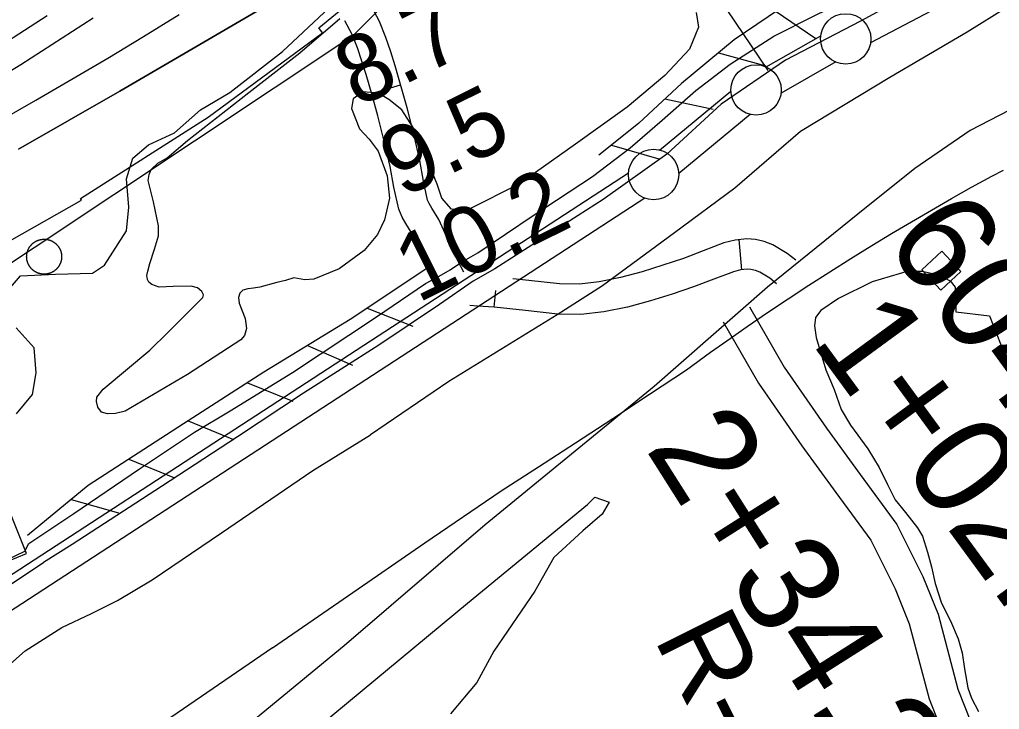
# Model space of a CAD drawing. Extents: x 3715084 to 3753216, y 488173 to 513963.
# Drawn here: x 3731429 to 3732401, y 498105 to 498790 of the extents above; entities that cross this region are included whole.
import ezdxf

# ---------------------------------------------------------------- set-up
doc = ezdxf.new("R2010")
doc.units = 0
for name, color, linetype in [('V-BLDG-OTLN', 7, 'Continuous'), ('V-CHAN-DOCK', 7, 'Continuous'), ('V-FLOD-BASE', 7, 'Continuous'), ('V-LEVE-TOET', 7, 'Continuous'), ('V-RAIL-TRAK', 7, 'Continuous'), ('V-RIVR-EDGE', 7, 'Continuous'), ('V-RIVR-RANG', 7, 'Continuous'), ('V-RIVR-RANG-IDEN', 7, 'Continuous'), ('V-ROAD-CNTR', 7, 'Continuous'), ('V-RRAP-FSHR', 7, 'Continuous'), ('V-RRAP-RVMT', 7, 'Continuous'), ('V-SITE-VEGE', 7, 'Continuous'), ('V-SURV-IDEN', 7, 'Continuous'), ('V-SURV-LINE', 7, 'Continuous'), ('V-TOPO-DPTH', 7, 'Continuous'), ('V-TOPO-MINR', 7, 'Continuous'), ('V-TOPO-SHOR', 7, 'Continuous'), ('V-TOPO-WATR', 7, 'Continuous')]:
    doc.layers.add(name, color=color, linetype=linetype)

msp = doc.modelspace()

# ---------------------------------------------------------------- linework, layer by layer
at = {"layer": 'V-BLDG-OTLN'}
msp.add_lwpolyline([(3732324.12, 498541.61), (3732343.99, 498560.18), (3732362.92, 498539.94), (3732343.04, 498521.36)], close=True, dxfattribs=at)
at = {"layer": 'V-CHAN-DOCK'}
for points in [[(3731436.97, 498560.3), (3731437.07, 498560.59), (3731437.17, 498560.87), (3731437.29, 498561.15), (3731437.4, 498561.43), (3731437.52, 498561.71), (3731437.65, 498561.98), (3731437.78, 498562.26), (3731437.91, 498562.53), (3731438.05, 498562.8), (3731438.2, 498563.07), (3731438.34, 498563.33), (3731438.5, 498563.59), (3731438.66, 498563.85), (3731438.82, 498564.1), (3731438.98, 498564.35), (3731439.16, 498564.6), (3731439.33, 498564.85), (3731439.51, 498565.09), (3731439.7, 498565.33), (3731439.89, 498565.57), (3731440.08, 498565.8), (3731440.27, 498566.04), (3731440.47, 498566.26), (3731440.68, 498566.48), (3731440.89, 498566.71), (3731441.1, 498566.92), (3731441.31, 498567.13), (3731441.53, 498567.34), (3731441.76, 498567.55), (3731441.98, 498567.75), (3731442.21, 498567.94), (3731442.45, 498568.14), (3731442.69, 498568.33), (3731442.93, 498568.51), (3731443.17, 498568.69), (3731443.41, 498568.86), (3731443.66, 498569.04), (3731443.92, 498569.21), (3731444.17, 498569.37), (3731444.43, 498569.53), (3731444.69, 498569.68), (3731444.96, 498569.83), (3731445.22, 498569.97), (3731445.49, 498570.11), (3731445.76, 498570.25), (3731446.03, 498570.38), (3731446.31, 498570.51), (3731446.58, 498570.63), (3731446.87, 498570.74), (3731447.15, 498570.85), (3731447.43, 498570.96), (3731447.71, 498571.06), (3731448, 498571.16), (3731448.29, 498571.25), (3731448.58, 498571.33), (3731448.87, 498571.41), (3731449.17, 498571.49), (3731449.46, 498571.56), (3731449.75, 498571.62), (3731450.05, 498571.69), (3731450.35, 498571.74), (3731450.65, 498571.79), (3731450.95, 498571.84), (3731451.25, 498571.88), (3731451.55, 498571.91), (3731451.85, 498571.94), (3731452.15, 498571.96), (3731452.45, 498571.98), (3731452.76, 498572), (3731453.06, 498572), (3731453.36, 498572.01), (3731453.67, 498572), (3731453.97, 498572), (3731454.27, 498571.98), (3731454.57, 498571.97), (3731454.87, 498571.94), (3731455.18, 498571.91), (3731455.48, 498571.88), (3731455.78, 498571.84), (3731456.08, 498571.79), (3731456.37, 498571.74), (3731456.67, 498571.69), (3731456.97, 498571.63), (3731457.26, 498571.56), (3731457.56, 498571.49), (3731457.85, 498571.42), (3731458.14, 498571.34), (3731458.44, 498571.25), (3731458.72, 498571.16), (3731459.01, 498571.06), (3731459.29, 498570.96), (3731459.58, 498570.86), (3731459.86, 498570.75), (3731460.14, 498570.63), (3731460.42, 498570.51), (3731460.69, 498570.38), (3731460.97, 498570.26), (3731461.24, 498570.12), (3731461.51, 498569.98), (3731461.77, 498569.84)], [(3731461.77, 498569.84), (3731462.04, 498569.69), (3731462.3, 498569.53), (3731462.56, 498569.38), (3731462.81, 498569.21), (3731463.06, 498569.04), (3731463.31, 498568.88), (3731463.56, 498568.7), (3731463.8, 498568.52), (3731464.04, 498568.33), (3731464.28, 498568.15), (3731464.51, 498567.95), (3731464.74, 498567.76), (3731464.97, 498567.56), (3731465.19, 498567.35), (3731465.41, 498567.14), (3731465.63, 498566.93), (3731465.84, 498566.72), (3731466.05, 498566.5), (3731466.25, 498566.27), (3731466.45, 498566.05), (3731466.65, 498565.82), (3731466.85, 498565.58), (3731467.03, 498565.35), (3731467.22, 498565.11), (3731467.4, 498564.86), (3731467.57, 498564.62), (3731467.75, 498564.37), (3731467.91, 498564.11), (3731468.07, 498563.86), (3731468.23, 498563.6), (3731468.39, 498563.34), (3731468.54, 498563.08), (3731468.68, 498562.81), (3731468.82, 498562.54), (3731468.96, 498562.27), (3731469.09, 498562), (3731469.21, 498561.72), (3731469.33, 498561.45), (3731469.45, 498561.17), (3731469.56, 498560.89), (3731469.67, 498560.6), (3731469.77, 498560.32), (3731469.86, 498560.03), (3731469.96, 498559.74), (3731470.04, 498559.45), (3731470.12, 498559.16), (3731470.2, 498558.86), (3731470.27, 498558.57), (3731470.33, 498558.28), (3731470.4, 498557.98), (3731470.45, 498557.68), (3731470.5, 498557.38), (3731470.54, 498557.08), (3731470.58, 498556.78), (3731470.62, 498556.48), (3731470.65, 498556.18), (3731470.67, 498555.88), (3731470.69, 498555.58), (3731470.7, 498555.27), (3731470.71, 498554.97)], [(3731450.66, 498537.53), (3731450.37, 498537.58), (3731450.07, 498537.63), (3731449.77, 498537.69), (3731449.48, 498537.76), (3731449.18, 498537.83), (3731448.89, 498537.91), (3731448.6, 498537.99), (3731448.31, 498538.07), (3731448.02, 498538.16), (3731447.73, 498538.26), (3731447.45, 498538.36), (3731447.16, 498538.47), (3731446.88, 498538.58), (3731446.6, 498538.69), (3731446.32, 498538.81), (3731446.05, 498538.94), (3731445.77, 498539.07), (3731445.5, 498539.2), (3731445.23, 498539.34), (3731444.97, 498539.49), (3731444.7, 498539.64), (3731444.44, 498539.79), (3731444.19, 498539.95), (3731443.93, 498540.11), (3731443.68, 498540.28), (3731443.43, 498540.45), (3731443.18, 498540.62), (3731442.94, 498540.8), (3731442.7, 498540.99), (3731442.46, 498541.18), (3731442.23, 498541.37), (3731442, 498541.57), (3731441.77, 498541.77), (3731441.55, 498541.97), (3731441.33, 498542.18), (3731441.11, 498542.39), (3731440.9, 498542.61), (3731440.69, 498542.83), (3731440.48, 498543.05), (3731440.28, 498543.28), (3731440.09, 498543.51), (3731439.89, 498543.74), (3731439.71, 498543.98), (3731439.52, 498544.22), (3731439.34, 498544.46), (3731439.17, 498544.71), (3731439, 498544.96), (3731438.83, 498545.21), (3731438.66, 498545.46), (3731438.5, 498545.72), (3731438.35, 498545.98), (3731438.2, 498546.25), (3731438.06, 498546.51), (3731437.92, 498546.78), (3731437.78, 498547.05), (3731437.65, 498547.32), (3731437.53, 498547.6), (3731437.41, 498547.88), (3731437.29, 498548.16), (3731437.18, 498548.44), (3731437.07, 498548.72), (3731436.97, 498549.01), (3731436.88, 498549.29), (3731436.79, 498549.58), (3731436.7, 498549.87), (3731436.62, 498550.16), (3731436.54, 498550.46), (3731436.47, 498550.75), (3731436.4, 498551.05), (3731436.35, 498551.34), (3731436.29, 498551.64), (3731436.24, 498551.94), (3731436.2, 498552.24), (3731436.15, 498552.54), (3731436.12, 498552.84), (3731436.09, 498553.14), (3731436.07, 498553.44), (3731436.05, 498553.75), (3731436.04, 498554.05), (3731436.03, 498554.35), (3731436.02, 498554.65), (3731436.03, 498554.96), (3731436.04, 498555.26), (3731436.05, 498555.56), (3731436.07, 498555.86), (3731436.09, 498556.17), (3731436.12, 498556.47), (3731436.15, 498556.77), (3731436.19, 498557.07), (3731436.24, 498557.37), (3731436.29, 498557.67), (3731436.34, 498557.96), (3731436.4, 498558.26), (3731436.47, 498558.55), (3731436.54, 498558.85), (3731436.61, 498559.14), (3731436.7, 498559.44), (3731436.78, 498559.73), (3731436.87, 498560.02), (3731436.97, 498560.3)], [(3731470.71, 498554.97), (3731470.71, 498554.67), (3731470.71, 498554.37), (3731470.7, 498554.06), (3731470.69, 498553.76), (3731470.67, 498553.46), (3731470.65, 498553.16), (3731470.62, 498552.85), (3731470.59, 498552.55), (3731470.55, 498552.26), (3731470.5, 498551.96), (3731470.45, 498551.66), (3731470.4, 498551.36), (3731470.34, 498551.06), (3731470.27, 498550.77), (3731470.2, 498550.47), (3731470.13, 498550.18), (3731470.04, 498549.89), (3731469.96, 498549.6), (3731469.87, 498549.31), (3731469.77, 498549.02), (3731469.67, 498548.74), (3731469.56, 498548.45), (3731469.46, 498548.17), (3731469.34, 498547.89), (3731469.22, 498547.61), (3731469.09, 498547.34), (3731468.96, 498547.07), (3731468.83, 498546.79), (3731468.69, 498546.53), (3731468.54, 498546.26), (3731468.39, 498545.99), (3731468.24, 498545.73), (3731468.08, 498545.48), (3731467.92, 498545.22), (3731467.75, 498544.97), (3731467.58, 498544.72), (3731467.41, 498544.47), (3731467.23, 498544.23), (3731467.04, 498543.99), (3731466.85, 498543.75), (3731466.66, 498543.52), (3731466.46, 498543.29), (3731466.26, 498543.06), (3731466.06, 498542.84), (3731465.85, 498542.62), (3731465.64, 498542.4), (3731465.42, 498542.19), (3731465.21, 498541.98), (3731464.98, 498541.78), (3731464.75, 498541.58), (3731464.52, 498541.38), (3731464.29, 498541.19), (3731464.05, 498541), (3731463.81, 498540.81), (3731463.57, 498540.63), (3731463.33, 498540.46), (3731463.08, 498540.29), (3731462.82, 498540.12), (3731462.57, 498539.96), (3731462.31, 498539.8), (3731462.05, 498539.64), (3731461.79, 498539.49), (3731461.52, 498539.35), (3731461.25, 498539.21), (3731460.98, 498539.08), (3731460.71, 498538.95), (3731460.43, 498538.82), (3731460.16, 498538.7), (3731459.87, 498538.58), (3731459.59, 498538.47), (3731459.31, 498538.37), (3731459.02, 498538.26), (3731458.74, 498538.17), (3731458.45, 498538.08), (3731458.16, 498537.99), (3731457.87, 498537.91), (3731457.57, 498537.83), (3731457.28, 498537.76), (3731456.98, 498537.7), (3731456.69, 498537.64), (3731456.39, 498537.58), (3731456.09, 498537.53), (3731455.79, 498537.49), (3731455.49, 498537.45), (3731455.19, 498537.41), (3731454.89, 498537.38), (3731454.59, 498537.36), (3731454.29, 498537.34), (3731453.98, 498537.33), (3731453.68, 498537.32), (3731453.38, 498537.32), (3731453.08, 498537.32), (3731452.77, 498537.33), (3731452.47, 498537.34), (3731452.17, 498537.36), (3731451.87, 498537.38), (3731451.56, 498537.41), (3731451.26, 498537.44), (3731450.96, 498537.48), (3731450.66, 498537.53)]]:
    msp.add_lwpolyline(points, dxfattribs=at)
at = {"layer": 'V-FLOD-BASE'}
for points in [[(3732385.46, 498860.31), (3732337.41, 498828.72), (3732263.44, 498788.3), (3732188.83, 498749.77), (3732124.98, 498706.17), (3732071.23, 498656.26), (3732008, 498611.4), (3731900.52, 498542.55), (3731879.03, 498530.54), (3731845.52, 498507.17)], [(3731845.52, 498507.17), (3731785.45, 498466.73), (3731710.85, 498419.36), (3731645.1, 498375.77), (3731569.86, 498326.49), (3731481.34, 498269), (3731452.89, 498251.31)], [(3731398.25, 498215.29), (3731452.89, 498251.31)]]:
    msp.add_lwpolyline(points, dxfattribs=at)
at = {"layer": 'V-LEVE-TOET'}
for points in [[(3731699.94, 498439.92), (3731783.04, 498494.86), (3731831.78, 498527.95), (3731843.03, 498534.19), (3731856.15, 498541.69), (3731867.4, 498549.18), (3731883.64, 498558.54), (3731938.63, 498595.38), (3731997.37, 498634.09), (3732034.86, 498662.81), (3732066.73, 498690.29), (3732099.85, 498719.64), (3732134.21, 498745.86), (3732177.33, 498773.33), (3732217.94, 498793.93), (3732277.92, 498823.27), (3732336.66, 498859.48), (3732367.27, 498876.96), (3732382.27, 498888.2), (3732392.9, 498894.45), (3732400.42, 498898.04)], [(3732408.66, 498801.82), (3732369.29, 498777.47), (3732292.44, 498732.52), (3732203.71, 498678.83), (3732138.72, 498622.63), (3732078.73, 498578.3), (3732007.5, 498525.85), (3731962.51, 498497.13), (3731855.04, 498430.95), (3731777.27, 498377.8)], [(3731438.34, 498269.98), (3731482.74, 498299.82), (3731547.84, 498344.3), (3731602.46, 498380.61), (3731638.1, 498401.88), (3731699.94, 498439.92)], [(3731500.42, 498200.57), (3731526.29, 498213.52), (3731560.43, 498234.21), (3731629.28, 498280.74), (3731720.04, 498342.39), (3731777.27, 498377.8)], [(3731358.16, 498221.77), (3731365, 498229.58), (3731434.35, 498262.4), (3731438.34, 498269.98)], [(3731222.63, 498010.08), (3731233.49, 498014.87), (3731298.21, 498058.22), (3731346.55, 498091.03), (3731358.59, 498097.4), (3731369.04, 498105.55), (3731387.57, 498122.23), (3731434.5, 498163.54), (3731470.8, 498186.62), (3731500.42, 498200.57)]]:
    msp.add_lwpolyline(points, dxfattribs=at)
at = {"layer": 'V-RAIL-TRAK'}
for points in [[(3732114.67, 498459.84), (3732130.7, 498471.26), (3732150.88, 498485.34), (3732171.2, 498499.22), (3732191.64, 498512.91), (3732212.22, 498526.41), (3732232.93, 498539.71), (3732253.76, 498552.8), (3732274.72, 498565.7), (3732294.27, 498577.62), (3732313.92, 498589.36), (3732333.68, 498600.93), (3732353.54, 498612.32), (3732373.5, 498623.52), (3732393.57, 498634.55), (3732405.39, 498640.37)], [(3731679.81, 498166.46), (3731755.37, 498218.61), (3731831.02, 498270.62), (3731906.77, 498322.49), (3731943.8, 498346.14), (3731980.71, 498369.97), (3732017.5, 498393.98), (3732054.18, 498418.16), (3732090.74, 498442.52), (3732114.67, 498459.84)], [(3731679.81, 498166.46), (3731555.77, 498081.73), (3731430.95, 497996.6), (3731300.41, 497909.09), (3731231.09, 497865.12)]]:
    msp.add_lwpolyline(points, dxfattribs=at)
at = {"layer": 'V-RIVR-EDGE'}
for points in [[(3731416.09, 498519.43), (3731429.94, 498535.6), (3731464.76, 498537.32), (3731501.39, 498538.43), (3731513.41, 498546.2), (3731535.11, 498580.37), (3731537.57, 498603.78), (3731535.24, 498632), (3731541.29, 498652.39), (3731556.93, 498665.56), (3731582.77, 498677.5), (3731608.64, 498700.25), (3731637.5, 498717.59), (3731689.83, 498758.28), (3731772.27, 498835.52)], [(3731426, 498398.74), (3731441.66, 498417.91), (3731445.31, 498439.51), (3731443.57, 498464.13), (3731425.61, 498483.99)], [(3731358.94, 498228.41), (3731435.86, 498260.04), (3731398.27, 498353.78)]]:
    msp.add_lwpolyline(points, dxfattribs=at)
at = {"layer": 'V-RIVR-RANG'}
msp.add_line((3732171.63, 498739.52), (3731602.8, 499586.19), dxfattribs=at)
at = {"layer": 'V-ROAD-CNTR'}
for p, q in [((3731778.31, 498716.69), (3731807.08, 498725.17)), ((3732145.77, 498541.7), (3732143.1, 498571.58)), ((3731899.77, 498504.61), (3731901.6, 498520.99))]:
    msp.add_line(p, q, dxfattribs=at)
for points in [[(3733715.57, 498954.14), (3733490.9, 498921.32), (3733259.48, 498888.54), (3733051.28, 498857.49), (3732876.96, 498828.74), (3732784.88, 498814.94), (3732717.77, 498804.69), (3732646.3, 498789.1), (3732562.5, 498763.31), (3732493.54, 498739.57), (3732430.27, 498709.84), (3732372.27, 498679.78), (3732317.45, 498642.1), (3732260.82, 498596.91), (3732170.98, 498524.46), (3732058.55, 498426.03), (3731890.92, 498288.7), (3731751.05, 498168.7), (3731580.79, 498028.32), (3731483.88, 497948.43), (3731408.15, 497888)], [(3731869.65, 498539.29), (3731864.16, 498549.95), (3731854.75, 498570.34), (3731844.9, 498591.65), (3731838.01, 498602.94), (3731835.39, 498607.38), (3731833.9, 498610.88), (3731829.84, 498629.54), (3731826.18, 498650.15), (3731820.07, 498676.32), (3731813.58, 498702.22), (3731807.67, 498723.18), (3731801.55, 498743.96), (3731797.23, 498757.92), (3731792.55, 498772.27), (3731786, 498788.11), (3731778.12, 498802.89)], [(3731844.51, 498522.6), (3731837.2, 498536.79), (3731827.52, 498557.76), (3731818.39, 498577.5), (3731812.29, 498587.5), (3731808.57, 498593.8), (3731805.19, 498601.72), (3731800.4, 498623.74), (3731796.79, 498644.11), (3731790.91, 498669.26), (3731784.58, 498694.5), (3731778.84, 498714.87), (3731772.82, 498735.29), (3731768.64, 498748.84), (3731764.38, 498761.87), (3731758.84, 498775.29), (3731751.65, 498788.76)], [(3732199.14, 498551.11), (3732190.73, 498558), (3732176.46, 498566.39), (3732167.87, 498569.63), (3732159.15, 498571.62), (3732150.73, 498572.26), (3732138.93, 498571.2), (3732127.93, 498568.26), (3732107.35, 498560.35), (3732087.73, 498552.99), (3732067.25, 498546.16), (3732046.67, 498539.64), (3732025.42, 498533.89), (3732004.12, 498529.61), (3731984.49, 498527.44), (3731964.85, 498527.77), (3731934.22, 498530.96), (3731918.49, 498532.71)], [(3732180.13, 498527.9), (3732173.51, 498533.32), (3732163.47, 498539.23), (3732159.21, 498540.83), (3732154.64, 498541.87), (3732150.93, 498542.16), (3732144.18, 498541.55), (3732137.22, 498539.69), (3732118, 498532.3), (3732097.75, 498524.71), (3732076.53, 498517.63), (3732055.12, 498510.85), (3732032.3, 498504.68), (3732008.73, 498499.94), (3731985.88, 498497.41), (3731963.04, 498497.8), (3731931.01, 498501.13), (3731900.02, 498504.58), (3731883.29, 498505.54), (3731875.91, 498506.32)], [(3732153.3, 498505.03), (3732187.59, 498445.12), (3732229.57, 498384.44), (3732263.14, 498338.54), (3732299.43, 498288.98), (3732325.18, 498237.51), (3732340.36, 498200.01), (3732360, 498125.44), (3732379.37, 498076.29)], [(3732127.26, 498490.13), (3732162.19, 498429.1), (3732205.12, 498367.05), (3732238.93, 498320.83), (3732273.73, 498273.3), (3732297.82, 498225.14), (3732311.84, 498190.52), (3732331.44, 498116.09), (3732351.46, 498065.29)]]:
    msp.add_lwpolyline(points, dxfattribs=at)
at = {"layer": 'V-RRAP-FSHR'}
for p, q in [((3732178.7, 498798.56), (3732219.18, 498771.25)), ((3732122.33, 498756.92), (3732169.47, 498744.17)), ((3732069.4, 498711.15), (3732117.15, 498700.95)), ((3732016.46, 498665.43), (3732063.31, 498651.69)), ((3731773.9, 498503.6), (3731819.35, 498485.73)), ((3731714.56, 498466.5), (3731759.3, 498446.94)), ((3731655.05, 498429.64), (3731700.25, 498411.16)), ((3731596.19, 498391.76), (3731641.38, 498373.28)), ((3731537.4, 498353.75), (3731582.65, 498335.38)), ((3731480.11, 498313.71), (3731527.16, 498300.63))]:
    msp.add_line(p, q, dxfattribs=at)
for points in [[(3728004.36, 498122.76), (3728249.57, 498078.76), (3728561.47, 498063.71), (3728941.93, 498053.37), (3729895.33, 498086.11), (3730231.16, 498125.42), (3730543.47, 498170.09), (3730885.51, 498262.37), (3731364.17, 498511.08), (3731760.76, 498774.83), (3732302.4, 499315.14), (3732839.9, 499636.89)], [(3732355.05, 498904.54), (3732342.35, 498883.34), (3732313.96, 498861.69), (3732243.93, 498823.59), (3732183.05, 498800.22), (3732137.92, 498769.94), (3732085.92, 498726.52), (3732043.61, 498687.15), (3732005.19, 498656.42), (3732003.83, 498655.46)], [(3731832.25, 498542.27), (3731756.92, 498492.34), (3731671.51, 498440.23), (3731591.53, 498388.76), (3731497.03, 498327.64), (3731436.91, 498278.13)]]:
    msp.add_lwpolyline(points, dxfattribs=at)
at = {"layer": 'V-RRAP-RVMT'}
for p, q in [((3731726.07, 498781.74), (3731834.36, 498871.07)), ((3731729.41, 498776.64), (3731726.07, 498781.74)), ((3731616.13, 498693.11), (3731729.41, 498776.64)), ((3731489.35, 498612.5), (3731616.13, 498693.11)), ((3731357.34, 498535.55), (3731490.37, 498610.68)), ((3731490.37, 498610.68), (3731489.35, 498612.5))]:
    msp.add_line(p, q, dxfattribs=at)
at = {"layer": 'V-SITE-VEGE'}
for points in [[(3732100.21, 498797.09), (3732102.73, 498782.55), (3732093.87, 498760.43), (3732069.21, 498734.52), (3732031.9, 498702.93), (3731980.69, 498666.29), (3731925.05, 498627.12), (3731873.84, 498601.22), (3731857.41, 498601.86), (3731847.93, 498612.61), (3731843.51, 498626.51), (3731828.35, 498662.55), (3731819.51, 498682.78), (3731808.14, 498700.48), (3731795.5, 498710.6), (3731784.76, 498716.92), (3731769.59, 498718.2), (3731760.1, 498711.25), (3731758.2, 498701.77), (3731766.42, 498681.54), (3731775.89, 498671.42), (3731784.74, 498659.41), (3731793.58, 498634.75), (3731796.1, 498612.62), (3731791.03, 498591.14), (3731784.08, 498576.6), (3731770.79, 498560.8), (3731746.14, 498542.48), (3731720.85, 498532.38), (3731712, 498531.75), (3731701.05, 498533.58), (3731692.9, 498531.05), (3731684.22, 498529.05), (3731667.27, 498524.38), (3731661.09, 498523.31), (3731655.44, 498522.89), (3731650.44, 498521.43), (3731647.56, 498518.39), (3731646.26, 498514.31), (3731646.94, 498508.65), (3731652.78, 498493.41), (3731654.26, 498483.55), (3731652.05, 498476.57), (3731648.38, 498472.09), (3731595.75, 498437.69), (3731533.66, 498401.55), (3731524.06, 498399.15), (3731516.17, 498398.72), (3731510.25, 498400.41), (3731506.54, 498405.53), (3731505.21, 498410.92), (3731505.72, 498415.26), (3731512, 498423.31), (3731558.17, 498462.02), (3731576.53, 498479.85), (3731610.74, 498514.05), (3731611.39, 498516.95), (3731609.93, 498520.23), (3731605.44, 498523.77), (3731599.12, 498525.32), (3731581.23, 498525.12), (3731567.55, 498524.55), (3731560.17, 498527.02), (3731557.4, 498529.38), (3731555.81, 498532.01), (3731555.27, 498536.08), (3731556.18, 498540.43), (3731558.39, 498548.06), (3731562.94, 498562.16), (3731566.71, 498575.33), (3731566.94, 498585.2), (3731561.85, 498609.25), (3731556.51, 498630.28), (3731557.54, 498636.34), (3731559.63, 498641.08), (3731566.05, 498647.55), (3731575.5, 498652.85), (3731595.57, 498670.02), (3731656.44, 498717.6), (3731707.02, 498756.78), (3731746.86, 498790.9)], [(3731648.96, 498024.68), (3731873.31, 498210.95), (3731992.64, 498308.86), (3731999.81, 498316.02), (3732014.12, 498311.24), (3732006.96, 498299.3), (3731987.87, 498282.59), (3731959.23, 498256.32), (3731940.14, 498222.89), (3731899.56, 498163.19), (3731882.86, 498132.14), (3731856.6, 498101.1)]]:
    msp.add_lwpolyline(points, dxfattribs=at)
at = {"layer": 'V-SURV-LINE'}
for points in [[(3732367.12, 498816.58), (3732273.39, 498766.9)], [(3732169.73, 498743.06), (3732223.93, 498773.94)], [(3732238.78, 498747.88), (3732184.58, 498717)], [(3732063.98, 498660.52), (3732134.85, 498719)], [(3732153.94, 498695.86), (3732083.07, 498637.38)], [(3730860.87, 497874.8), (3732033.19, 498637.91)], [(3732049.54, 498612.76), (3730877.22, 497849.65)]]:
    msp.add_lwpolyline(points, dxfattribs=at)
for centre in [(3732248.71, 498770.8), (3732159.8, 498720.14), (3732058.12, 498636.24)]:
    msp.add_circle(centre, 25, dxfattribs=at)
at = {"layer": 'V-TOPO-DPTH'}
for points in [[(3731719.08, 498830.35), (3731528.63, 498718.88), (3731427.78, 498661.39)], [(3731357.18, 498700.91), (3731430.27, 498745.25), (3731501.94, 498791.82)], [(3731357.18, 498700.91), (3731430.27, 498745.25), (3731501.94, 498791.82)]]:
    msp.add_lwpolyline(points, dxfattribs=at)
at = {"layer": 'V-TOPO-MINR'}
for points in [[(3731357.18, 498700.91), (3731430.27, 498745.25), (3731501.94, 498791.82)], [(3731387.6, 498749.76), (3731456.43, 498793.87)], [(3731408.96, 498689.37), (3731444.99, 498709.87), (3731480.83, 498730.68), (3731516.56, 498751.7), (3731552.01, 498773.17), (3731587.2, 498795.06)]]:
    msp.add_lwpolyline(points, dxfattribs=at)
at = {"layer": 'V-TOPO-SHOR'}
for points in [[(3732310.53, 498540.31), (3732275.13, 498529.57), (3732241.62, 498513.15), (3732223.92, 498501.15), (3732218.86, 498494.2), (3732217.59, 498485.98), (3732219.49, 498474.6), (3732228.96, 498442.36), (3732237.17, 498422.76), (3732244.11, 498403.17), (3732253.59, 498387.36), (3732270.65, 498363.97), (3732282.02, 498345.63), (3732290.23, 498328.56), (3732297.81, 498313.39), (3732307.92, 498300.74), (3732319.92, 498285.57), (3732324.97, 498277.35), (3732330.02, 498261.55), (3732333.81, 498247.01), (3732337.6, 498230.57), (3732343.91, 498210.98), (3732352.75, 498193.27), (3732360.33, 498175.57), (3732364.12, 498161.66), (3732366.65, 498145.86), (3732369.8, 498126.9), (3732373.59, 498116.78), (3732380.53, 498103.5)], [(3732310.53, 498540.31), (3732324.44, 498540.3), (3732339.61, 498537.14), (3732352.25, 498530.81), (3732357.3, 498524.49), (3732357.92, 498499.84), (3732391.42, 498496.03), (3732420.47, 498422.06), (3732457.1, 498334.82), (3732479.21, 498276.03), (3732504.47, 498215.34), (3732541.1, 498126.83), (3732601.79, 498151.46), (3732631.47, 498084.45), (3732839.46, 498164.02), (3732843.88, 498152.64), (3732880.55, 498169.06), (3732887.49, 498151.99), (3732903.3, 498157.67), (3732914.03, 498129.22), (3732804.67, 498081.22)]]:
    msp.add_lwpolyline(points, dxfattribs=at)
at = {"layer": 'V-TOPO-WATR'}
msp.add_lwpolyline([(3731427.78, 498661.39), (3731528.63, 498718.88), (3731719.08, 498830.35)], dxfattribs=at)

# ---------------------------------------------------------------- texts
at = {"layer": 'V-RIVR-RANG'}
for s, p in [('8.7', (3731764.11, 498701.91)), ('9.5', (3731808.87, 498612.48)), ('10.2', (3731823.87, 498508.26))]:
    msp.add_text(s, height=67, rotation=26.44833, dxfattribs=at).set_placement(p)
at = {"layer": 'V-RIVR-RANG-IDEN'}
msp.add_text('R-81.6', height=83, rotation=296.59039, dxfattribs=at).set_placement((3732057.84, 498176.27))
at = {"layer": 'V-SURV-IDEN'}
for s, rotation, p in [('604+60.2', 306.04399, (3732285.81, 498570.71)), ('1+02.3', 306.2378, (3732213.28, 498470.53)), ('2+34.2', 302.34972, (3732049.19, 498364.53))]:
    msp.add_text(s, height=100, rotation=rotation, dxfattribs=at).set_placement(p)

doc.saveas('drawing.dxf')
